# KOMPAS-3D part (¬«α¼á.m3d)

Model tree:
1. Эскиз:1
2. Операция выдавливания:1
     Расстояние 1 = 2; Расстояние 2 = 0.3
3. Эскиз:3
4. Операция выдавливания:3
     Расстояние 1 = 2; Расстояние 2 = 0.3
5. Скругление:2
     Радиус = 1; Хорда = 0.2
6. Скругление:3
     Радиус = 0.2; Хорда = 0.2
7. Эскиз:4
8. Вырезать элемент выдавливания:1
     Расстояние 2 = 1; Расстояние 1 = 47.805
9. Массив по сетке:1  (with: Операция выдавливания:3, Скругление:2, Скругление:3, Вырезать элемент выдавливания:1)  (labels: Экземпляр ( 1, 1 ); Экземпляр ( 2, 1 ); Экземпляр ( 3, 1 ); Экземпляр ( 4, 1 ))
     N 1 = 7; Шаг 1 = 116; Угол раствора = 90; N 2 = 1; Номер 1 = 1; Номер 2 = 1
10. Эскиз:5
11. Операция выдавливания:4
     Расстояние 1 = 1; Расстояние 2 = 1
12. Эскиз:6
13. Операция выдавливания:5
     Расстояние 1 = 2; Расстояние 2 = 1
14. Эскиз:7
15. Операция выдавливания:6
     Расстояние 1 = 1; Расстояние 2 = 1
16. Массив по концентрической сетке:1  (with: Операция выдавливания:6)  (labels: Экземпляр ( 1, 1 ); Экземпляр ( 1, 2 ); Экземпляр ( 1, 3 ); Экземпляр ( 1, 4 ))
     N 2 = 5; Шаг 2 = 360; Номер 2 = 1
17. Эскиз:9
18. Вырезать элемент выдавливания:3
     Расстояние 2 = 6.05758; Расстояние 1 = 1
19. Массив по концентрической сетке:3  (with: Вырезать элемент выдавливания:3)  (labels: Экземпляр ( 1, 1 ); Экземпляр ( 1, 2 ); Экземпляр ( 1, 3 ); Экземпляр ( 1, 4 ))
     N 2 = 5; Шаг 2 = 360; Номер 2 = 1
20. Эскиз:10
21. Операция выдавливания:7
     Расстояние 1 = 1; Расстояние 2 = 1
22. Массив по концентрической сетке:4  (with: Операция выдавливания:7)  (labels: Экземпляр ( 1, 1 ); Экземпляр ( 1, 2 ); Экземпляр ( 1, 3 ); Экземпляр ( 1, 4 ))
     N 2 = 5; Шаг 2 = 360; Номер 2 = 1
23. Скругление:4
     Радиус = 1
24. Скругление:6
     Радиус = 1
25. Скругление:7
     Радиус = 1
26. Скругление:8
     Радиус = 1
27. Эскиз:11
28. Операция выдавливания:8
     Расстояние 1 = 10
29. Эскиз:13
30. Вырезать элемент выдавливания:4
     Расстояние 1 = 106.009
31. Эскиз:14
32. Операция выдавливания:9
     Расстояние 1 = 0.5; Расстояние 2 = 1.5
33. Эскиз:15
34. Операция выдавливания:10
     Расстояние 1 = 1; Расстояние 2 = 1
35. Эскиз:16
36. Операция выдавливания:11
     Расстояние 1 = 1; Расстояние 2 = 1
37. Эскиз:17
38. Вырезать элемент выдавливания:5
     Расстояние 1 = 3
39. Эскиз:18
40. Операция выдавливания:12
     Расстояние 1 = 1; Расстояние 2 = 1

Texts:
  Сплав АЛ8  ГОСТ 1583-93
